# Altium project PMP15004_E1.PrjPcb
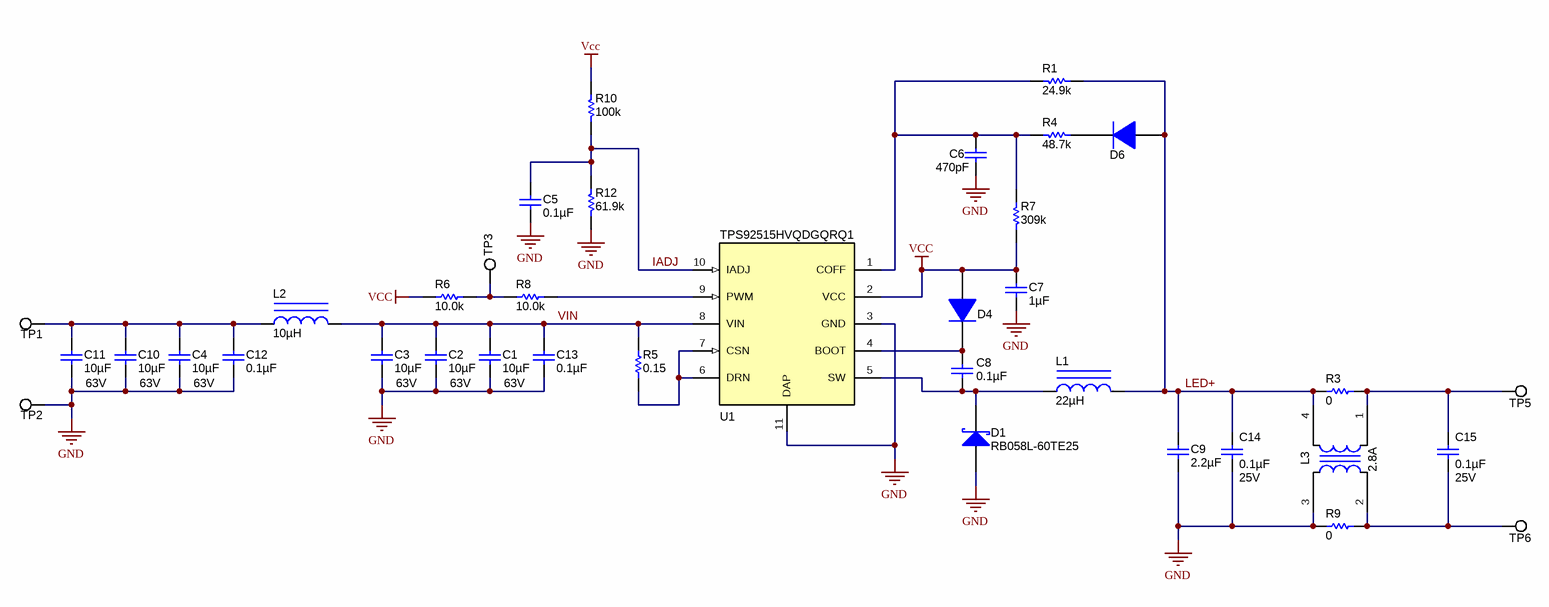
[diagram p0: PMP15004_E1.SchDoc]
TID: PMP15004; TechSupport: http://www.ti.com/support; SCH_Rev: E1; PRJ_Title: PMP15004; PRJ_Number: PMP15004; PRJ_Engineer: Irwin Nederbragt; PRJ_Customer: Public Release; PCB_Rev: E1; PCB_Layout: Kerry Murphy; CopyrightYear: 2016
1 sheet, 37 parts. Net scope: global (net labels, ports and power ports of the same name join across sheets).
Board file: PMP15004_E1.PcbDoc

## Sheet PMP15004_E1.SchDoc
size 431 x 279 mm; Date: Not shown in title block; ApprovedBy: Not shown in title block; CheckedBy: Not shown in title block; Author: Not shown in title block; CompanyName: Not shown in title block; Engineer: Not shown in title block; Organization: Not shown in title block; Address1: Not shown in title block; Address2: Not shown in title block; Address3: Not shown in title block; Address4: Not shown in title block; DocumentNumber: 1; Revision: Use project parameter SCH_Rev; SheetNumber: 1; SheetTotal: 2; PageSetup: Record=PageOptions¦CenterHorizontal=True¦CenterVertical=True¦PrintScale=0.61¦XCorrection=1.00¦YCorrection=1.00¦PrintKind=0¦BorderSize=5000000¦LeftOffset=0¦BottomOffset=0¦Orientation=2¦PaperLength=1000¦PaperWidth=1000¦Scale=100¦PaperSource=15¦PrintQuality=600¦MediaType=1¦DitherType=10¦PrintScaleMode=1¦PaperKind=Letter

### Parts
C1  ValueDisplayed: 10µF  Value2: 63V  [1210]  (hidden comment: GRM32ER71J106KA12L)
C2  ValueDisplayed: 10µF  Value2: 63V  [1210]  (hidden comment: GRM32ER71J106KA12L)
C3  ValueDisplayed: 10µF  Value2: 63V  [1210]  (hidden comment: GRM32ER71J106KA12L)
C4  ValueDisplayed: 10µF  Value2: 63V  [1210]  (hidden comment: GRM32ER71J106KA12L)
C5  ValueDisplayed: 0.1µF  [0603_HV]  (hidden comment: GCM188R71C104KA37J)
C6  ValueDisplayed: 470pF  [0603_HV]  (hidden comment: GCM1885C1H471JA16D)
C7  ValueDisplayed: 1µF  [0603_HV]  (hidden comment: GCM188R71C105KA64D)
C8  ValueDisplayed: 0.1µF  [0603_HV]  (hidden comment: GCM188R71C104KA37J)
C9  ValueDisplayed: 2.2µF  [1210]  (hidden comment: CGA5L3X7S2A225M160AB)
C10  ValueDisplayed: 10µF  Value2: 63V  [1210]  (hidden comment: GRM32ER71J106KA12L)
C11  ValueDisplayed: 10µF  Value2: 63V  [1210]  (hidden comment: GRM32ER71J106KA12L)
C12  ValueDisplayed: 0.1µF  [0603_HV]  (hidden comment: GRM188R72A104KA35D)
C13  ValueDisplayed: 0.1µF  [0603_HV]  (hidden comment: GRM188R72A104KA35D)
C14  ValueDisplayed: 0.1µF  Value2: 25V  [0603_HV]  (hidden comment: GRM188R71E104KA01D)
C15  ValueDisplayed: 0.1µF  Value2: 25V  [0603_HV]  (hidden comment: GRM188R71E104KA01D)
D1  RB058L-60TE25  [SMA]
D4  MMSD4148T1G  [SOD-123]  (value not drawn)
D6  MMSD4148T1G  [SOD-123]  (value not drawn)
L1  ValueDisplayed: 22µH  [XAL5050]  (hidden comment: XAL5050-223MEB)
L2  ValueDisplayed: 10µH  [WE-SPC_4838]  (hidden comment: 74408943100)
L3  ValueDisplayed: 2.8A  [TDK_ACM4520]  (hidden comment: ACM4520-421-2P-T000)
R1  ValueDisplayed: 24.9k  [0603_HV]  (hidden comment: CRCW060324K9FKEA)
R3  ValueDisplayed: 0  [0603_HV]  (hidden comment: CRCW06030000Z0EA)
R4  ValueDisplayed: 48.7k  [0603_HV]  (hidden comment: CRCW060348K7FKEA)
R5  ValueDisplayed: 0.15  [1206]  (hidden comment: WSL1206R1500FEA)
R6  ValueDisplayed: 10.0k  [0603_HV]  (hidden comment: CRCW060310K0FKEA)
R7  ValueDisplayed: 309k  [0603_HV]  (hidden comment: CRCW0603309KFKEA)
R8  ValueDisplayed: 10.0k  [0603_HV]  (hidden comment: CRCW060310K0FKEA)
R9  ValueDisplayed: 0  [0603_HV]  (hidden comment: CRCW06030000Z0EA)
R10  ValueDisplayed: 100k  [0603_HV]  (hidden comment: CRCW0603100KFKEA)
R12  ValueDisplayed: 61.9k  [0603_HV]  (hidden comment: CRCW060361K9FKEA)
TP1  5015  [S2751-46R]  (value not drawn)
TP2  5015  [S2751-46R]  (value not drawn)
TP3  5015  [S2751-46R]  (value not drawn)
TP5  5015  [S2751-46R]  (value not drawn)
TP6  5015  [S2751-46R]  (value not drawn)
U1  TPS92515HVQDGQRQ1  [DGQ0010A_N]

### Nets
GND: C1.2 C2.2 C3.2 C4.2 C5.1 C6.2 C7.2 C9.2 C10.2 C11.2 C12.2 C13.2 C14.2 D1.2(A) L3.3 R9.1 R12.1 TP2.1 U1.3(GND) U1.11(DAP)
Vcc: C7.1 D4.2(A) R6.1 R7.1 R10.2 U1.2(VCC)
IADJ: C5.2 R10.1 R12.2 U1.10(IADJ)
LED+: C9.1 C14.1 D6.2(A) L1.2 L3.4 R1.1 R3.1
VIN: C1.1 C2.1 C3.1 C13.1 L2.2 R5.2 U1.8(VIN)
NetC4_1: C4.1 C10.1 C11.1 C12.1 L2.1 TP1.1
NetC6_1: C6.1 R1.2 R4.1 R7.2 U1.1(COFF)
NetC8_1: C8.1 D1.1(K) L1.1 U1.5(SW)
NetC8_2: C8.2 D4.1(K) U1.4(BOOT)
NetC15_1: C15.1 L3.1 R3.2 TP5.1
NetC15_2: C15.2 L3.2 R9.2 TP6.1
NetD6_1: D6.1(K) R4.2
NetR5_1: R5.1 U1.6(DRN) U1.7(CSN)
NetR6_2: R6.2 R8.1 TP3.1
NetR8_2: R8.2 U1.9(PWM)

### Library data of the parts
C1-C4 C10 C11 = GRM32ER71J106KA12L: CAP, CERM, 10 µF, 63 V, +/- 10%, X7R, 1210; Manufacturer: MuRata; Polarized: N; CompType: Capacitor; Value: 10uF; U/M: EA; Cap_F: 0.00001; Tolerance_%: 10; Value1: Unknown; VDC_V: 63; TaMin_C: -55; TaMax_C: 125; AEC Category: Q200
C5 C8 = GCM188R71C104KA37J: CAP, CERM, 0.1 µF, 16 V, +/- 10%, X7R, 0603_095; Manufacturer: MuRata; Polarized: N; CompType: Capacitor; Value: 0.1uF; U/M: EA; Cap_F: 0.0000001; Tolerance_%: 10; Value1: Unknown; VDC_V: 16; Value2: 16V; TaMin_C: -55; TaMax_C: 125; Cap_Case: 0603
C6 = GCM1885C1H471JA16D: CAP, CERM, 470 pF, 50 V, +/- 5%, C0G/NP0, 0603_095; Manufacturer: MuRata; Polarized: N; CompType: Capacitor; Value: 470pF; U/M: EA; Cap_F: 0.00000000047; Tolerance_%: 5; Value1: Unknown; VDC_V: 50; Value2: 50V; TaMin_C: -55; TaMax_C: 125; Cap_Case: 0603
C7 = GCM188R71C105KA64D: CAP, CERM, 1 µF, 16 V, +/- 10%, X7R, 0603_095; Manufacturer: MuRata; Polarized: N; CompType: Capacitor; Value: 1uF; U/M: EA; Cap_F: 0.000001; Tolerance_%: 10; Value1: Unknown; VDC_V: 16; Value2: 16V; TaMin_C: -55; TaMax_C: 125; Cap_Case: 0603
C9 = CGA5L3X7S2A225M160AB: CAP, CERM, 2.2 µF, 100 V, +/- 20%, X7S, 1206_190; Manufacturer: TDK; Polarized: N; CompType: Capacitor; Value: 2.2uF; U/M: EA; Cap_F: 0.0000022; Tolerance_%: 20; Value1: Unknown; VDC_V: 100; Value2: 100V; TaMin_C: -55; TaMax_C: 125; Cap_Case: 1206
C12 C13 = GRM188R72A104KA35D: CAP, CERM, 0.1 µF, 100 V, +/- 10%, X7R, 0603; Manufacturer: MuRata; Polarized: N; CompType: Capacitor; Value: 0.1uF; U/M: EA; Cap_F: 0.0000001; Tolerance_%: 10; Value1: Unknown; VDC_V: 100; Value2: 100V; TaMin_C: -55; TaMax_C: 125; Cap_Case: 0603; AEC Category: Q200
C14 C15 = GRM188R71E104KA01D: CAP, CERM, 0.1 µF, 25 V, +/- 10%, X7R, 0603; Manufacturer: MuRata; Polarized: N; CompType: Capacitor; Value: 0.1uF; U/M: EA; Cap_F: 0.0000001; Tolerance_%: 10; Value1: Unknown; VDC_V: 25; TaMin_C: -55; TaMax_C: 125; Cap_Case: 0603; AEC Category: Q200
D1 = Diode_Schottky: Diode, Schottky, 60V, 3A, SMA; Manufacturer: Rohm Semiconductor; U/M: EA; Value: 640mV @ 3A; Speed: Fast Recovery =< 500ns, > 200mA (Io); Current - Reverse Leakage @ Vr: 4µA @ 60V
D4 D6 = MMSD4148T1G: Diode, Switching, 100 V, 0.2 A, SOD-123; Manufacturer: ON Semiconductor; U/M: EA; Vf_V: 1; Value: 100V; Value1: 0.2A; Value2: 1V; Io_A: 0.2; Vr_V: 100; TJmax_C: 150
L1 = XAL5050-223MEB: Inductor, Shielded, Composite, 22 µH, 3.4 A, 0.1 ohm, SMD; Manufacturer: Coilcraft; Value: 22uH; Ind_H: 22.0E-6; Imax_A: 3.4; Irms: 3.4A @ 40C rise; Isat: 3.6A @ 30% inductance drop; DCR_ohm: 0.1; Value1: 0.1 ohm; Value2: 3.4A; AEC Category: Q200
L2 = 74408943100: Inductor, Shielded Drum Core, Ferrite, 10 µH, 1.65 A, 0.082 ohm, SMD; Manufacturer: Wurth Elektronik; Value: 10uH; Ind_H: 10.0E-6; Imax_A: 1.65; Irms: 1.65A @ 40C rise; Isat: 2.1A @ 35% inductance drop; DCR_ohm: 0.082; Value2: 1.65A; AEC Category: Q200
L3 = ACM4520-421-2P-T000: Coupled inductor, 2.8 A, 0.055 ohm, SMD; Manufacturer: TDK; SymbolCreator: a0799628; DCR_ohm: 0.055
R1 = CRCW060324K9FKEA: RES, 24.9 k, 1%, 0.1 W, 0603; Manufacturer: Vishay-Dale; CompType: Resistor; Value: 24.9k; Res_ohm: 24900; Value_Code: 24k9; Tolerance_%: 1; Power_W: 0.1; Value2: 0.1W; VDC_V: 75; TempCo: 100 ppm/C; EIA_Code: E96; U/M: EA; AEC Category: Q200
R3 R9 = CRCW06030000Z0EA: RES, 0, 5%, 0.1 W, 0603; Manufacturer: Vishay-Dale; CompType: Resistor; Value: 0; Value_Code: 0000; Tolerance_%: 5; Power_W: 0.1; Value2: 0.1W; VDC_V: 75; TempCo: 200 ppm/C; EIA_Code: E24; U/M: EA; AEC Category: Q200
R4 = CRCW060348K7FKEA: RES, 48.7 k, 1%, 0.1 W, 0603; Manufacturer: Vishay-Dale; CompType: Resistor; Value: 48.7k; Res_ohm: 48700; Value_Code: 48k7; Tolerance_%: 1; Power_W: 0.1; Value2: 0.1W; VDC_V: 75; TempCo: 100 ppm/C; EIA_Code: E96; U/M: EA
R5 = WSL1206R1500FEA: RES, 0.15, 1%, 0.25 W, 1206; Manufacturer: Vishay-Dale; CompType: Resistor; Value: 0.15; Value_Code: R150; Tolerance_%: 1; Power_W: 0.25; Value2: 0.25W; TempCo: 75 ppm/C; SizeArea_mm2: 5.12; SizeX_mm: 3.2; SizeY_mm: 1.6; SizeZ_mm: 1.35; EIA_Code: E96; U/M: EA; AEC Category: Q200; AEC Qualified: N
R6 R8 = CRCW060310K0FKEA: RES, 10.0 k, 1%, 0.1 W, 0603; Manufacturer: Vishay-Dale; CompType: Resistor; Value: 10.0k; Res_ohm: 10000; Value_Code: 10k0; Tolerance_%: 1; Power_W: 0.1; Value2: 0.1W; VDC_V: 75; TempCo: 100 ppm/C; EIA_Code: E96; U/M: EA; AEC Category: Q200
R7 = CRCW0603309KFKEA: RES, 309 k, 1%, 0.1 W, 0603; Manufacturer: Vishay-Dale; CompType: Resistor; Value: 309k; Res_ohm: 309000; Tolerance_%: 1; Power_W: 0.1; Value2: 0.1W; VDC_V: 75; TempCo: 100 ppm/C; EIA_Code: E96; U/M: EA
R10 = CRCW0603100KFKEA: RES, 100 k, 1%, 0.1 W, 0603; Manufacturer: Vishay-Dale; CompType: Resistor; Value: 100k; Res_ohm: 100000; Tolerance_%: 1; Power_W: 0.1; Value2: 0.1W; VDC_V: 75; TempCo: 100 ppm/C; EIA_Code: E96; U/M: EA
R12 = CRCW060361K9FKEA: RES, 61.9 k, 1%, 0.1 W, 0603; Manufacturer: Vishay-Dale; CompType: Resistor; Value: 61.9k; Res_ohm: 61900; Value_Code: 61k9; Tolerance_%: 1; Power_W: 0.1; Value2: 0.1W; VDC_V: 75; TempCo: 100 ppm/C; EIA_Code: E96; U/M: EA
TP1-TP3 TP5 TP6 = 5015: Test Point, Miniature, SMT; Manufacturer: Keystone; CompType: Test Point Loop
U1 = TPS92515QDGQRQ1: 2A, 65V, Automotive Buck LED Driver with Integrated N-FET, DGQ0010A; Alternate PartNumber: TPS92515QDGQQ1; Manufacturer: Texas Instruments; SymbolCreator: Altium; CompType: IC; U/M: EA

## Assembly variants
001: not fitted D6 L4 R3 R4 R7 R9 R12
